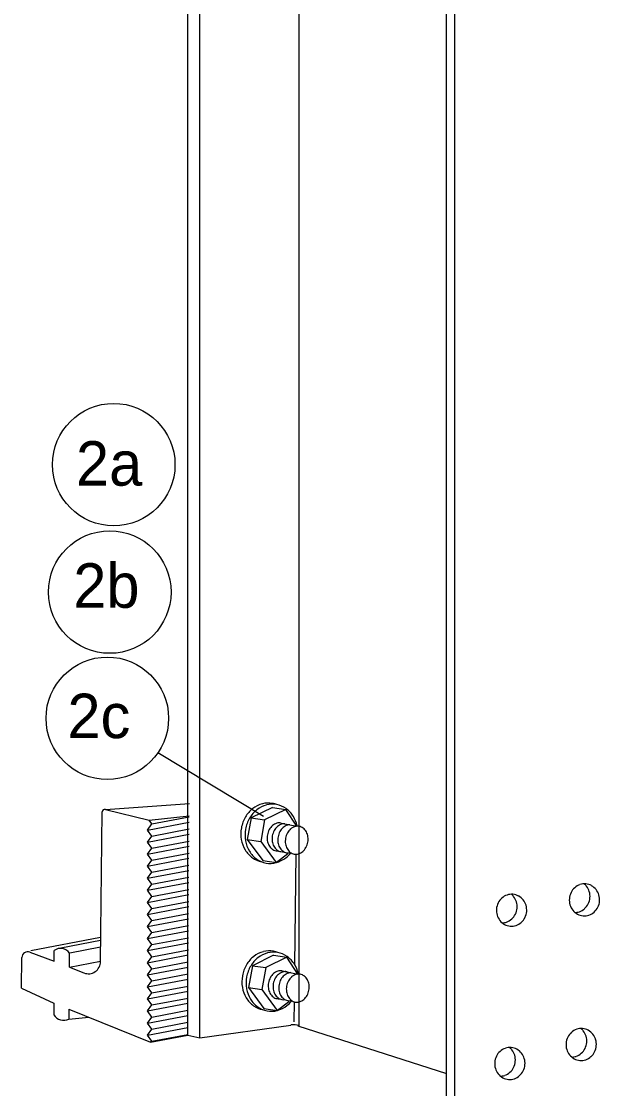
# Model space of a CAD drawing. Extents: x 12.3 to 19.6, y 5.8 to 16.1.
# Drawn here: x 13.054 to 14.169, y 8.839 to 10.897 of the extents above; entities that cross this region are included whole.
import ezdxf

# ---------------------------------------------------------------- set-up
doc = ezdxf.new("R2010")
doc.units = 0
doc.layers.add('DETL-LINE', color=7, linetype='Continuous')
doc.layers.add('DETL-NOTE', color=7, linetype='Continuous')

msp = doc.modelspace()

# ---------------------------------------------------------------- linework, layer by layer
at = {"layer": 'DETL-LINE'}
for p, q in [((13.3751, 8.942), (13.3751, 12.9888)), ((13.3981, 8.9369), (13.3981, 12.9888)), ((13.5899, 8.9603), (13.5899, 12.9888)), ((13.8741, 8.7423), (13.8741, 12.9888)), ((13.8901, 8.7359), (13.8901, 12.9888)), ((13.2163, 9.377), (13.3783, 9.3887)), ((13.2069, 9.0838), (13.2102, 9.3726)), ((13.2163, 9.377), (13.3006, 9.3564)), ((13.3006, 9.3564), (13.3781, 9.3649)), ((13.5385, 9.3812), (13.4976, 9.3613)), ((13.5643, 9.3774), (13.5233, 9.3574)), ((13.5385, 9.3812), (13.5643, 9.3774)), ((13.5856, 9.3449), (13.5643, 9.3774)), ((13.2972, 9.3377), (13.378, 9.3531)), ((13.2972, 9.3377), (13.3059, 9.3494)), ((13.3059, 9.3494), (13.3006, 9.3564)), ((13.3059, 9.3494), (13.3781, 9.3631)), ((13.4976, 9.3613), (13.4899, 9.3191)), ((13.4976, 9.3613), (13.5233, 9.3574)), ((13.5233, 9.3574), (13.5157, 9.3153)), ((13.555, 9.3512), (13.5856, 9.3449)), ((13.3059, 9.3261), (13.2972, 9.3377)), ((13.2972, 9.3145), (13.3779, 9.3298)), ((13.2972, 9.3145), (13.3059, 9.3261)), ((13.3059, 9.3261), (13.3779, 9.3398)), ((13.3059, 9.3028), (13.2972, 9.3145)), ((13.2972, 9.2912), (13.3777, 9.3065)), ((13.2972, 9.2912), (13.3059, 9.3028)), ((13.3059, 9.3028), (13.3778, 9.3165)), ((13.4899, 9.3191), (13.5157, 9.3153)), ((13.4899, 9.3191), (13.5199, 9.2787)), ((13.5157, 9.3153), (13.5456, 9.2749)), ((13.3059, 9.2796), (13.2972, 9.2912)), ((13.2972, 9.2679), (13.3775, 9.2832)), ((13.3059, 9.2796), (13.3776, 9.2932)), ((13.5456, 9.2749), (13.568, 9.2922)), ((13.5816, 9.0773), (13.5838, 9.2909)), ((13.2972, 9.2679), (13.3059, 9.2796)), ((13.3059, 9.2563), (13.2972, 9.2679)), ((13.3059, 9.2563), (13.3774, 9.2699)), ((13.5199, 9.2787), (13.5456, 9.2749)), ((13.2972, 9.2447), (13.3774, 9.2599)), ((13.2972, 9.2447), (13.3059, 9.2563)), ((13.3059, 9.233), (13.2972, 9.2447)), ((13.3059, 9.233), (13.3773, 9.2466)), ((13.2972, 9.2214), (13.3772, 9.2366)), ((13.2972, 9.2214), (13.3059, 9.233)), ((13.3059, 9.2098), (13.2972, 9.2214)), ((13.3059, 9.2098), (13.3771, 9.2233)), ((13.2972, 9.1981), (13.377, 9.2133)), ((13.2972, 9.1981), (13.3059, 9.2098)), ((13.3059, 9.1865), (13.3769, 9.2)), ((13.3059, 9.1865), (13.2972, 9.1981)), ((13.2972, 9.1749), (13.3769, 9.19)), ((13.2972, 9.1749), (13.3059, 9.1865)), ((13.3059, 9.1632), (13.2972, 9.1749)), ((13.2972, 9.1516), (13.3767, 9.1667)), ((13.2972, 9.1516), (13.3059, 9.1632)), ((13.3059, 9.1632), (13.3768, 9.1767)), ((13.3059, 9.14), (13.2972, 9.1516)), ((13.2972, 9.1283), (13.3765, 9.1434)), ((13.2972, 9.1283), (13.3059, 9.14)), ((13.3059, 9.14), (13.3766, 9.1534)), ((13.0729, 9.1051), (13.2069, 9.1313)), ((13.1306, 9.1105), (13.2069, 9.1254)), ((13.3059, 9.1167), (13.2972, 9.1283)), ((13.2972, 9.1051), (13.3763, 9.1201)), ((13.3059, 9.1167), (13.3764, 9.1301)), ((13.071, 9.1023), (13.1176, 9.0846)), ((13.1176, 9.0846), (13.1176, 9.1053)), ((13.147, 9.0732), (13.147, 9.1003)), ((13.1481, 9.1011), (13.2069, 9.1126)), ((13.2972, 9.1051), (13.3059, 9.1167)), ((13.3059, 9.0934), (13.2972, 9.1051)), ((13.2972, 9.0818), (13.3762, 9.0968)), ((13.3059, 9.0934), (13.3763, 9.1068)), ((13.0544, 9.0328), (13.0553, 9.0916)), ((13.1473, 9.073), (13.2069, 9.0847)), ((13.2972, 9.0818), (13.3059, 9.0934)), ((13.3059, 9.0702), (13.2972, 9.0818)), ((13.3059, 9.0702), (13.3761, 9.0835)), ((13.5405, 9.0961), (13.4996, 9.0761)), ((13.5662, 9.0922), (13.5253, 9.0723)), ((13.5405, 9.0961), (13.5662, 9.0922)), ((13.5876, 9.0598), (13.5662, 9.0922)), ((13.147, 9.0732), (13.1751, 9.0621)), ((13.2972, 9.0585), (13.376, 9.0735)), ((13.2972, 9.0585), (13.3059, 9.0702)), ((13.3059, 9.0469), (13.2972, 9.0585)), ((13.3059, 9.0469), (13.3759, 9.0602)), ((13.4996, 9.0761), (13.4919, 9.034)), ((13.4996, 9.0761), (13.5253, 9.0723)), ((13.5253, 9.0723), (13.5177, 9.0301)), ((13.557, 9.0661), (13.5876, 9.0598)), ((13.2972, 9.0353), (13.3758, 9.0502)), ((13.2972, 9.0353), (13.3059, 9.0469)), ((13.3059, 9.0236), (13.2972, 9.0353)), ((13.3059, 9.0236), (13.3758, 9.0369)), ((13.0544, 9.0328), (13.1168, 9.004)), ((13.2972, 9.012), (13.3757, 9.0269)), ((13.2972, 9.012), (13.3059, 9.0236)), ((13.4919, 9.034), (13.5218, 8.9935)), ((13.4919, 9.034), (13.5177, 9.0301)), ((13.5177, 9.0301), (13.5476, 8.9897)), ((13.1168, 9.004), (13.1168, 8.9812)), ((13.3059, 9.0004), (13.2972, 9.012)), ((13.2972, 8.9887), (13.3755, 9.0036)), ((13.2972, 8.9887), (13.3059, 9.0004)), ((13.3059, 9.0004), (13.3756, 9.0136)), ((13.5476, 8.9897), (13.57, 9.007)), ((13.5805, 8.9678), (13.5809, 9.0064)), ((13.1462, 8.9922), (13.3036, 8.9284)), ((13.1462, 8.9922), (13.1462, 8.9729)), ((13.1462, 8.9729), (13.1845, 8.9766)), ((13.3059, 8.9771), (13.2972, 8.9887)), ((13.2972, 8.9655), (13.3753, 8.9803)), ((13.2972, 8.9655), (13.3059, 8.9771)), ((13.3059, 8.9771), (13.3754, 8.9903)), ((13.5218, 8.9935), (13.5476, 8.9897)), ((13.3059, 8.9538), (13.2972, 8.9655)), ((13.2972, 8.9422), (13.3752, 8.957)), ((13.2972, 8.9422), (13.3059, 8.9538)), ((13.3059, 8.9538), (13.3752, 8.967)), ((13.3981, 8.9369), (13.5738, 8.9617)), ((13.5874, 8.9601), (13.8741, 8.8683)), ((13.3059, 8.9306), (13.2972, 8.9422)), ((13.3036, 8.9284), (13.3751, 8.942)), ((13.3059, 8.9306), (13.3751, 8.9437)), ((13.3751, 8.942), (13.3981, 8.9369)), ((13.3059, 8.9306), (13.3036, 8.9284))]:
    msp.add_line(p, q, dxfattribs=at)
for centre, radius, start, end in [((13.5321, 9.3385), 0.0515, 104.7869, 128.1978), ((13.5402, 9.3361), 0.0515, 104.7869, 128.1978), ((13.5304, 9.3448), 0.045, 79.7015, 104.7869), ((13.5385, 9.3425), 0.045, 79.7015, 104.7869), ((13.5304, 9.3448), 0.045, 68.6074, 79.7015), ((13.5385, 9.3425), 0.045, 54.6162, 79.7015), ((13.2148, 9.3726), 0.00465, 71.7951, 180), ((13.5357, 9.3339), 0.0573, 128.1978, 149.573), ((13.5438, 9.3316), 0.0573, 128.1978, 149.573), ((13.5347, 9.3371), 0.0515, 31.2052, 54.6162), ((13.5419, 9.3302), 0.0645, 149.573, 169.7015), ((13.55, 9.3279), 0.0645, 149.573, 169.7015), ((13.5565, 9.3253), 0.0276, 130.9442, 151.3081), ((13.5534, 9.3289), 0.0228, 106.9936, 130.9442), ((13.5659, 9.3236), 0.0276, 130.9442, 151.3081), ((13.5518, 9.3338), 0.0177, 79.7015, 106.9936), ((13.5628, 9.3272), 0.0228, 106.9936, 130.9442), ((13.5613, 9.3321), 0.0177, 87.5517, 106.9936), ((13.5738, 9.3252), 0.0228, 106.9936, 130.9442), ((13.5723, 9.3301), 0.0177, 91.82, 106.9936), ((13.5884, 9.3224), 0.0228, 106.9936, 130.9442), ((13.5298, 9.3341), 0.0573, 11.8972, 31.2052), ((13.5868, 9.3273), 0.0177, 79.7015, 106.9936), ((13.5868, 9.3273), 0.0177, 52.4094, 79.7015), ((13.5419, 9.3302), 0.0645, 169.7015, 189.8301), ((13.55, 9.3279), 0.0645, 169.7015, 189.8301), ((13.5619, 9.3223), 0.0338, 169.7015, 188.095), ((13.5619, 9.3223), 0.0338, 151.3081, 169.7015), ((13.5713, 9.3206), 0.0338, 169.7015, 188.095), ((13.5713, 9.3206), 0.0338, 151.3081, 169.7015), ((13.5824, 9.3186), 0.0338, 169.7015, 188.095), ((13.5824, 9.3186), 0.0338, 151.3081, 169.7015), ((13.5769, 9.3216), 0.0276, 130.9442, 151.3081), ((13.5969, 9.3158), 0.0338, 151.3081, 169.7015), ((13.5915, 9.3188), 0.0276, 130.9442, 151.3081), ((13.5837, 9.3232), 0.0228, 28.4589, 52.4094), ((13.5795, 9.3209), 0.0276, 8.095, 28.4589), ((13.5734, 9.3201), 0.0338, 349.7015, 8.095), ((13.5348, 9.329), 0.0573, 189.8301, 211.2052), ((13.5429, 9.3267), 0.0573, 189.8301, 211.2052), ((13.5558, 9.3215), 0.0276, 188.095, 208.4589), ((13.5516, 9.3192), 0.0228, 208.4589, 232.4094), ((13.5652, 9.3197), 0.0276, 188.095, 208.4589), ((13.561, 9.3175), 0.0228, 208.4589, 232.4094), ((13.5763, 9.3177), 0.0276, 188.095, 208.4589), ((13.5721, 9.3155), 0.0228, 208.4589, 232.4094), ((13.5969, 9.3158), 0.0338, 169.7015, 188.095), ((13.5908, 9.3149), 0.0276, 188.095, 208.4589), ((13.5788, 9.3171), 0.0276, 310.9442, 331.3081), ((13.5734, 9.3201), 0.0338, 331.3081, 349.7015), ((13.5298, 9.326), 0.0515, 211.2052, 234.6162), ((13.5379, 9.3237), 0.0515, 211.2052, 234.6162), ((13.526, 9.3207), 0.045, 234.6162, 259.3813), ((13.5484, 9.3151), 0.0177, 232.4094, 259.7015), ((13.5484, 9.3151), 0.0177, 259.7015, 275.4752), ((13.5325, 9.3247), 0.0515, 284.7869, 308.1978), ((13.5579, 9.3134), 0.0177, 232.4094, 259.7015), ((13.5579, 9.3134), 0.0177, 259.7015, 278.1919), ((13.5689, 9.3114), 0.0177, 232.4094, 259.7015), ((13.5289, 9.3292), 0.0573, 308.1978, 321.1498), ((13.5689, 9.3114), 0.0177, 259.7015, 283.7656), ((13.5866, 9.3127), 0.0228, 208.4589, 232.4094), ((13.5834, 9.3086), 0.0177, 232.4094, 259.7015), ((13.5834, 9.3086), 0.0177, 259.7015, 286.9936), ((13.5819, 9.3135), 0.0228, 286.9936, 310.9442), ((13.5341, 9.3183), 0.045, 234.6162, 259.7015), ((13.5341, 9.3183), 0.045, 259.7015, 284.7869), ((14.1414, 9.2034), 0.0307, 131.5782, 153.6389), ((14.1405, 9.2044), 0.0294, 108.675, 131.5782), ((14.14, 9.2059), 0.0279, 85.1385, 108.675), ((14.1207, 9.211), 0.0294, 38.6988, 50.6152), ((14.14, 9.2059), 0.0279, 61.602, 85.1385), ((14.1197, 9.2102), 0.0307, 16.6381, 38.6988), ((14.1393, 9.2045), 0.0294, 38.6988, 61.602), ((14.1382, 9.2037), 0.0307, 16.6381, 38.6988), ((14.0009, 9.1835), 0.0307, 131.5782, 153.6389), ((14, 9.1845), 0.0294, 108.675, 131.5782), ((13.9995, 9.1859), 0.0279, 85.1385, 108.675), ((13.9803, 9.1911), 0.0294, 38.6988, 50.6152), ((13.9995, 9.1859), 0.0279, 61.602, 85.1385), ((13.9792, 9.1902), 0.0307, 16.6381, 38.6988), ((13.9988, 9.1846), 0.0294, 38.6988, 61.602), ((13.9978, 9.1837), 0.0307, 16.6381, 38.6988), ((14.1428, 9.2027), 0.0323, 175.1385, 196.6381), ((14.1428, 9.2027), 0.0323, 153.6389, 175.1385), ((14.1182, 9.2097), 0.0323, 333.6389, 355.1385), ((14.1182, 9.2097), 0.0323, 355.1385, 16.6381), ((14.1367, 9.2032), 0.0323, 333.6389, 355.1385), ((14.1367, 9.2032), 0.0323, 355.1385, 16.6381), ((14.0023, 9.1828), 0.0323, 175.1385, 196.6381), ((14.0023, 9.1828), 0.0323, 153.6389, 175.1385), ((13.9777, 9.1898), 0.0323, 333.6389, 355.1385), ((13.9777, 9.1898), 0.0323, 355.1385, 16.6381), ((13.9962, 9.1833), 0.0323, 333.6389, 355.1385), ((13.9962, 9.1833), 0.0323, 355.1385, 16.6381), ((14.1413, 9.2022), 0.0307, 196.6381, 218.6988), ((14.1402, 9.2014), 0.0294, 218.6988, 241.602), ((14.121, 9.2065), 0.0279, 271.2675, 288.675), ((14.1205, 9.208), 0.0294, 288.675, 311.5782), ((14.1196, 9.209), 0.0307, 311.5782, 333.6389), ((14.139, 9.2015), 0.0294, 288.675, 311.5782), ((14.1381, 9.2025), 0.0307, 311.5782, 333.6389), ((14.0008, 9.1823), 0.0307, 196.6381, 218.6988), ((13.9998, 9.1815), 0.0294, 218.6988, 241.602), ((13.9805, 9.1866), 0.0279, 271.2675, 288.675), ((13.98, 9.1881), 0.0294, 288.675, 311.5782), ((13.9791, 9.1891), 0.0307, 311.5782, 333.6389), ((13.9986, 9.1816), 0.0294, 288.675, 311.5782), ((13.9977, 9.1826), 0.0307, 311.5782, 333.6389), ((14.1395, 9.2001), 0.0279, 241.602, 265.1385), ((14.1395, 9.2001), 0.0279, 265.1385, 288.675), ((13.999, 9.1801), 0.0279, 241.602, 265.1385), ((13.999, 9.1801), 0.0279, 265.1385, 288.675), ((13.0669, 9.0915), 0.0116, 69.226, 179.1381), ((13.1299, 9.089), 0.0205, 33.6014, 126.8304), ((13.5341, 9.0533), 0.0515, 104.7869, 128.1978), ((13.5422, 9.051), 0.0515, 104.7869, 128.1978), ((13.5324, 9.0596), 0.045, 79.7015, 104.7869), ((13.5405, 9.0573), 0.045, 79.7015, 104.7869), ((13.5324, 9.0596), 0.045, 68.6074, 79.7015), ((13.5405, 9.0573), 0.045, 54.6162, 79.7015), ((13.1836, 9.0838), 0.0233, 248.6079, 360), ((13.5439, 9.0451), 0.0645, 149.573, 169.7015), ((13.5377, 9.0488), 0.0573, 128.1978, 149.573), ((13.5458, 9.0464), 0.0573, 128.1978, 149.573), ((13.5367, 9.052), 0.0515, 31.2052, 54.6162), ((13.5318, 9.049), 0.0573, 11.8972, 31.2052), ((13.5439, 9.0451), 0.0645, 169.7015, 189.8301), ((13.552, 9.0428), 0.0645, 149.573, 169.7015), ((13.5585, 9.0401), 0.0276, 130.9442, 151.3081), ((13.5554, 9.0437), 0.0228, 106.9936, 130.9442), ((13.5679, 9.0384), 0.0276, 130.9442, 151.3081), ((13.5538, 9.0487), 0.0177, 79.7015, 106.9936), ((13.5648, 9.042), 0.0228, 106.9936, 130.9442), ((13.5789, 9.0364), 0.0276, 130.9442, 151.3081), ((13.5633, 9.047), 0.0177, 79.7015, 106.9936), ((13.5758, 9.04), 0.0228, 106.9936, 130.9442), ((13.5743, 9.045), 0.0177, 91.82, 106.9936), ((13.5903, 9.0372), 0.0228, 106.9936, 130.9442), ((13.5888, 9.0422), 0.0177, 79.7015, 106.9936), ((13.5888, 9.0422), 0.0177, 52.4094, 79.7015), ((13.5857, 9.0381), 0.0228, 28.4589, 52.4094), ((13.552, 9.0428), 0.0645, 169.7015, 189.8301), ((13.5639, 9.0372), 0.0338, 169.7015, 188.095), ((13.5639, 9.0372), 0.0338, 151.3081, 169.7015), ((13.5733, 9.0355), 0.0338, 169.7015, 188.095), ((13.5733, 9.0355), 0.0338, 151.3081, 169.7015), ((13.5844, 9.0335), 0.0338, 169.7015, 188.095), ((13.5844, 9.0335), 0.0338, 151.3081, 169.7015), ((13.5989, 9.0307), 0.0338, 169.7015, 188.095), ((13.5989, 9.0307), 0.0338, 151.3081, 169.7015), ((13.5935, 9.0336), 0.0276, 130.9442, 151.3081), ((13.5815, 9.0358), 0.0276, 8.095, 28.4589), ((13.5754, 9.0349), 0.0338, 349.7015, 8.095), ((13.5368, 9.0439), 0.0573, 189.8301, 211.2052), ((13.5449, 9.0415), 0.0573, 189.8301, 211.2052), ((13.5578, 9.0363), 0.0276, 188.095, 208.4589), ((13.5536, 9.034), 0.0228, 208.4589, 232.4094), ((13.5504, 9.0299), 0.0177, 232.4094, 259.7015), ((13.5672, 9.0346), 0.0276, 188.095, 208.4589), ((13.563, 9.0323), 0.0228, 208.4589, 232.4094), ((13.5782, 9.0326), 0.0276, 188.095, 208.4589), ((13.5741, 9.0303), 0.0228, 208.4589, 232.4094), ((13.5928, 9.0298), 0.0276, 188.095, 208.4589), ((13.5886, 9.0275), 0.0228, 208.4589, 232.4094), ((13.5808, 9.032), 0.0276, 310.9442, 331.3081), ((13.5754, 9.0349), 0.0338, 331.3081, 349.7015), ((13.5318, 9.0409), 0.0515, 211.2052, 234.6162), ((13.5399, 9.0385), 0.0515, 211.2052, 234.6162), ((13.528, 9.0355), 0.045, 234.6162, 259.3813), ((13.5361, 9.0332), 0.045, 234.6162, 259.7015), ((13.5504, 9.0299), 0.0177, 259.7015, 275.4752), ((13.5345, 9.0395), 0.0515, 284.7869, 308.1978), ((13.5599, 9.0282), 0.0177, 232.4094, 259.7015), ((13.5599, 9.0282), 0.0177, 259.7015, 278.1919), ((13.5709, 9.0262), 0.0177, 232.4094, 259.7015), ((13.5309, 9.0441), 0.0573, 308.1978, 321.1498), ((13.5709, 9.0262), 0.0177, 259.7015, 283.7656), ((13.5854, 9.0234), 0.0177, 232.4094, 259.7015), ((13.5854, 9.0234), 0.0177, 259.7015, 286.9936), ((13.5839, 9.0284), 0.0228, 286.9936, 310.9442), ((13.1363, 8.994), 0.0233, 213.1996, 294.9286), ((13.5361, 9.0332), 0.045, 259.7015, 284.7869), ((13.5788, 8.9259), 0.0362, 72.2475, 98.0414), ((14.1342, 8.9255), 0.0294, 108.675, 131.5782), ((14.1337, 8.927), 0.0279, 85.1385, 108.675), ((14.1145, 8.9321), 0.0294, 38.6988, 50.6152), ((14.1337, 8.927), 0.0279, 61.602, 85.1385), ((14.1365, 8.9238), 0.0323, 153.6389, 175.1385), ((14.1351, 8.9246), 0.0307, 131.5782, 153.6389), ((14.1134, 8.9313), 0.0307, 16.6381, 38.6988), ((14.1119, 8.9308), 0.0323, 355.1385, 16.6381), ((14.133, 8.9256), 0.0294, 38.6988, 61.602), ((14.132, 8.9248), 0.0307, 16.6381, 38.6988), ((14.1304, 8.9244), 0.0323, 355.1385, 16.6381), ((13.9967, 8.8888), 0.0294, 108.675, 131.5782), ((13.9962, 8.8903), 0.0279, 85.1385, 108.675), ((13.9769, 8.8954), 0.0294, 38.6988, 50.6152), ((13.9962, 8.8903), 0.0279, 61.602, 85.1385), ((13.9759, 8.8946), 0.0307, 16.6381, 38.6988), ((13.9954, 8.889), 0.0294, 38.6988, 61.602), ((14.1365, 8.9238), 0.0323, 175.1385, 196.6381), ((14.135, 8.9234), 0.0307, 196.6381, 218.6988), ((14.1133, 8.9301), 0.0307, 311.5782, 333.6389), ((14.1119, 8.9308), 0.0323, 333.6389, 355.1385), ((14.1304, 8.9244), 0.0323, 333.6389, 355.1385), ((13.999, 8.8871), 0.0323, 153.6389, 175.1385), ((13.9975, 8.8879), 0.0307, 131.5782, 153.6389), ((13.9743, 8.8942), 0.0323, 333.6389, 355.1385), ((13.9743, 8.8942), 0.0323, 355.1385, 16.6381), ((13.9944, 8.8881), 0.0307, 16.6381, 38.6988), ((13.9929, 8.8877), 0.0323, 355.1385, 16.6381), ((14.134, 8.9226), 0.0294, 218.6988, 241.602), ((14.1147, 8.9277), 0.0279, 271.2675, 288.675), ((14.1332, 8.9212), 0.0279, 241.602, 265.1385), ((14.1142, 8.9292), 0.0294, 288.675, 311.5782), ((14.1332, 8.9212), 0.0279, 265.1385, 288.675), ((14.1328, 8.9227), 0.0294, 288.675, 311.5782), ((14.1319, 8.9236), 0.0307, 311.5782, 333.6389), ((13.999, 8.8871), 0.0323, 175.1385, 196.6381), ((13.9974, 8.8867), 0.0307, 196.6381, 218.6988), ((13.9766, 8.8925), 0.0294, 288.675, 311.5782), ((13.9758, 8.8934), 0.0307, 311.5782, 333.6389), ((13.9943, 8.887), 0.0307, 311.5782, 333.6389), ((13.9929, 8.8877), 0.0323, 333.6389, 355.1385), ((13.9964, 8.8859), 0.0294, 218.6988, 241.602), ((13.9771, 8.891), 0.0279, 271.2675, 288.675), ((13.9957, 8.8845), 0.0279, 241.602, 265.1385), ((13.9957, 8.8845), 0.0279, 265.1385, 288.675), ((13.9952, 8.886), 0.0294, 288.675, 311.5782)]:
    msp.add_arc(centre, radius, start, end, dxfattribs=at)
at = {"layer": 'DETL-NOTE'}
msp.add_line((13.5213, 9.3638), (13.3176, 9.4865), dxfattribs=at)
for centre in [(13.2324, 10.0422), (13.2248, 9.7965), (13.2201, 9.5531)]:
    msp.add_circle(centre, 0.1181, dxfattribs=at)

# ---------------------------------------------------------------- texts
for s, p in [('2a', (13.1597, 10.0017)), ('2b', (13.1545, 9.7662)), ('2c', (13.1432, 9.5148))]:
    msp.add_text(s, height=0.0858, dxfattribs=at).set_placement(p)

doc.saveas('drawing.dxf')
